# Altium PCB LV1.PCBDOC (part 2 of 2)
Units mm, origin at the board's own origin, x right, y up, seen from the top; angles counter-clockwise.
Board outline 220.06 x 100 mm, 2 copper layers (Component Side, Bottom Layer), stack 0.325 mm thick; 185 components, 114 nets, 661 pads, 212 vias.
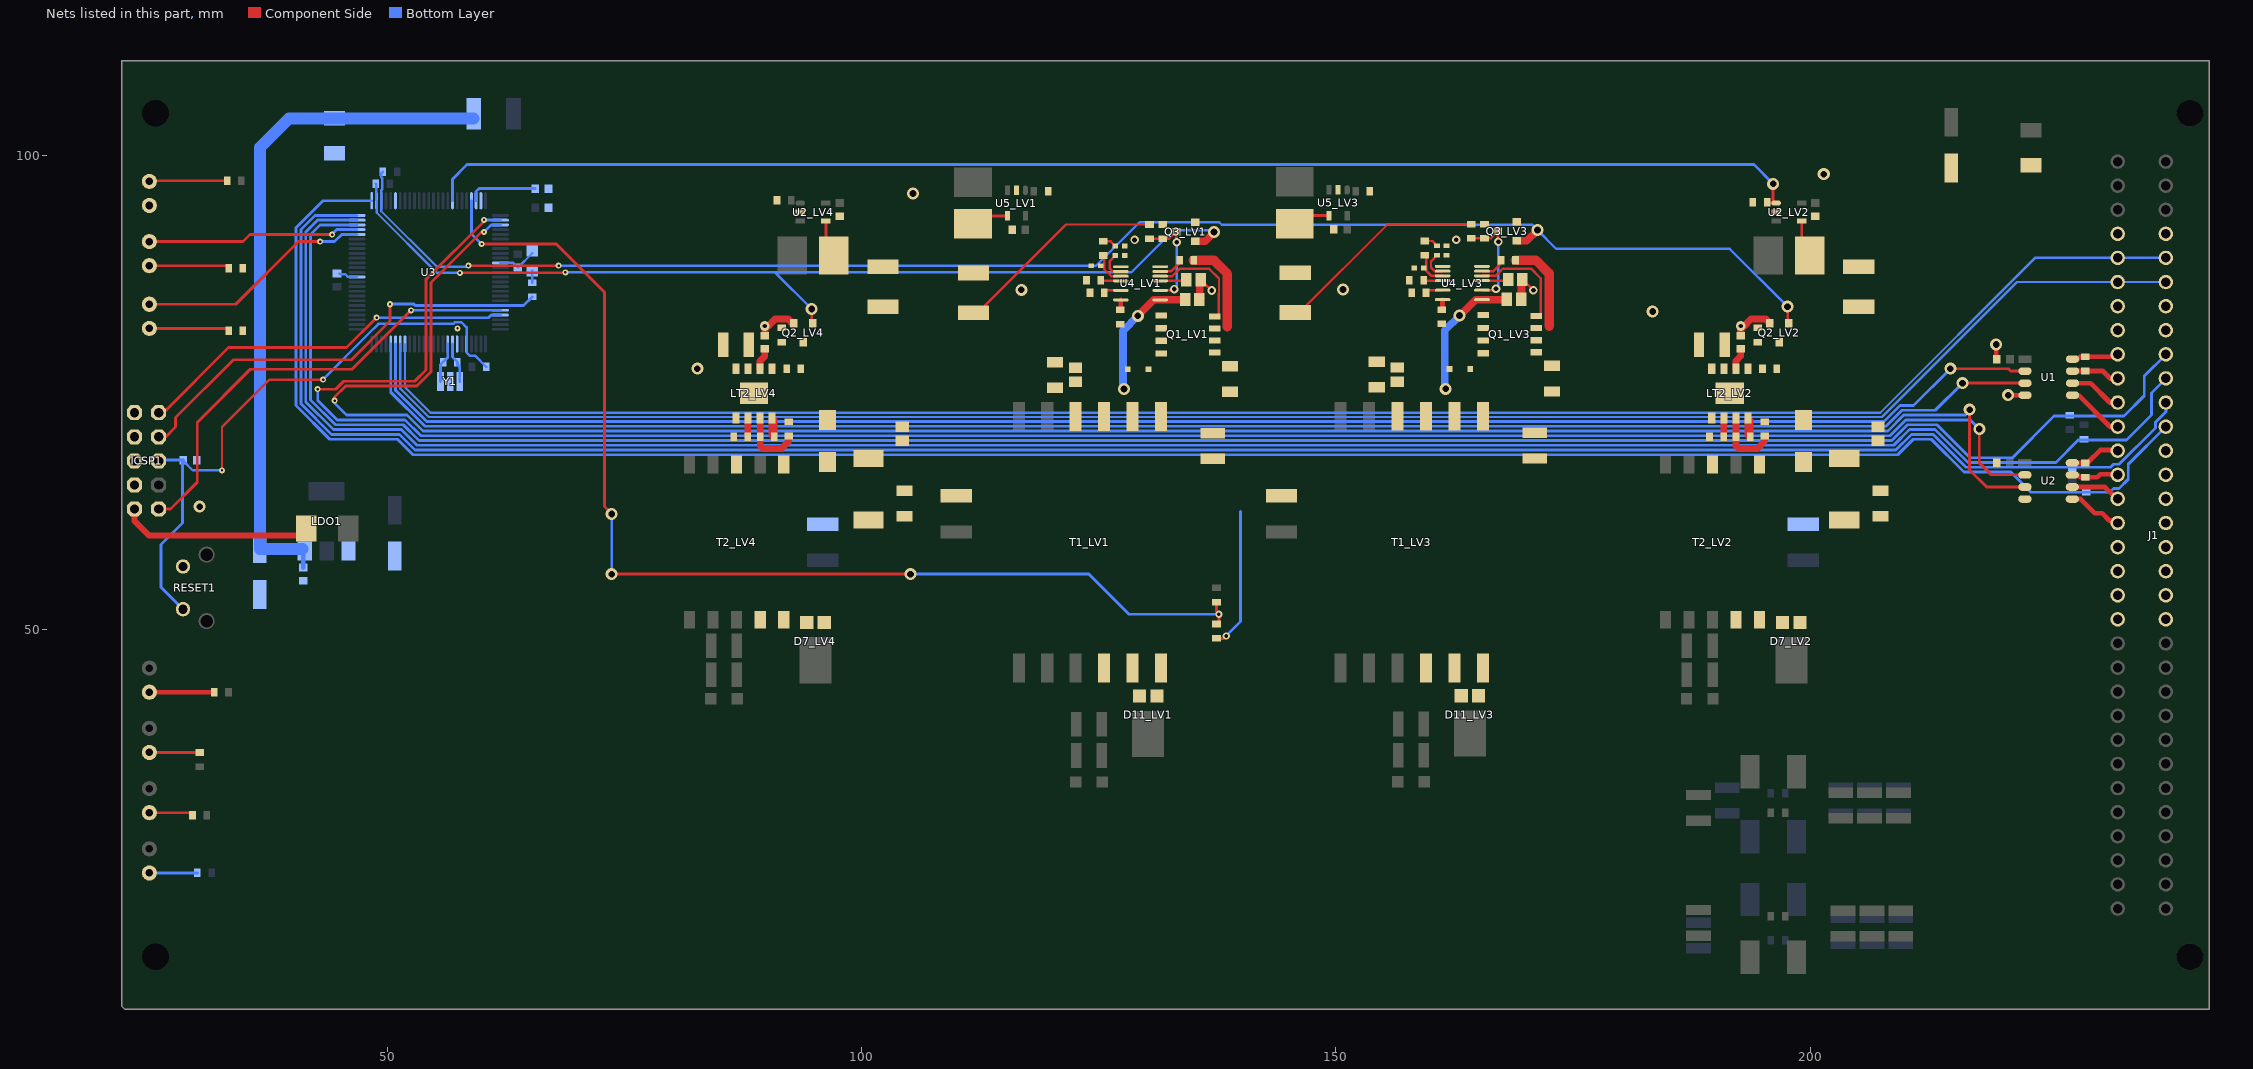
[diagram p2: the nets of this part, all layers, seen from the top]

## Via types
v1: diameter 1.27, hole 0.711, Component Side to Bottom Layer, 176 vias
v2: diameter 0.635, hole 0.254, Component Side to Bottom Layer, 17 vias
v3: diameter 0.762, hole 0.381, Component Side to Bottom Layer, 9 vias
v4: diameter 0.9, hole 0.5, Component Side to Bottom Layer, 8 vias
v5: diameter 1.016, hole 0.457, Component Side to Bottom Layer, 2 vias

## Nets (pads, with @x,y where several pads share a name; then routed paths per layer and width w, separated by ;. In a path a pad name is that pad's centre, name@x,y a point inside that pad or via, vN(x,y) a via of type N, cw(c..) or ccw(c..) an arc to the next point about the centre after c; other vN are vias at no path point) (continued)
A3: R5_LV2.2 U2_LV2.1 U3.93 | length 146
  Component Side w0.3: R5_LV2.2@195.52,94.994 U2_LV2.1@196.402,94.994 196.088,95.308 v1(196.088,97.028)
  Bottom Layer w0.3: U3.93@56.872,95.242 56.872,97.512 58.42,99.06 194.056,99.06 v1(196.088,97.028)
A_NTC: NTC.2 R_NTC.1 U3.97 | length 117.7
  Component Side w0.3: v2(59.944,90.678) 67.818,90.678 72.898,85.598 72.898,62.992 v1(73.66,62.23) ; v1(73.66,55.88) v1(105.156,55.88) ; v3@137.414,51.904 R_NTC.1@137.414,52.932 ; NTC.2@137.668,50.876 v3(137.668,51.65)
  Bottom Layer w0.3: U3.97@58.872,95.242 58.872,91.75 v2(59.944,90.678) ; v1(73.66,55.88) v1(73.66,62.23) ; v1(105.156,55.88) 123.952,55.88 128.182,51.65 v3(137.668,51.65)
ADRS0: J1.11 RADRS0.2 U3.76 | length 233.9
  Bottom Layer w0.3: U3.76@48.372,95.242 43.227,95.242 40.386,92.401 40.386,74.847 40.394,74.839 40.394,73.645 43.935,70.104 51.084,70.104 52.721,68.467 209.219,68.467 210.856,70.104 212.763,70.104 216.212,66.655 221.139,66.655 223.278,64.516 231.543,64.516 231.949,64.922 232.555,64.922 233.522,65.889 233.522,67.462 J1.11@237.49,71.43
ADRS1: J1.10 RADRS1.2 U3.75 | length 229.4
  Bottom Layer w0.3: U3.75@46.822,93.692 42.384,93.692 40.894,92.202 40.894,74.648 40.902,74.64 40.902,73.844 44.134,70.612 51.283,70.612 52.928,68.967 209.012,68.967 210.657,70.612 212.962,70.612 216.419,67.155 231.643,67.155 231.949,67.462 232.562,67.462 236.378,71.278 236.378,71.891 237.49,73.003 J1.10@237.49,73.97
ADRS2: J1.9 RADRS2.2 U3.74 | length 229
  Bottom Layer w0.3: U3.74@46.822,93.192 42.646,93.192 41.402,91.948 41.402,74.449 41.41,74.441 41.41,74.043 44.333,71.12 51.482,71.12 53.135,69.467 208.805,69.467 210.458,71.12 213.161,71.12 216.626,67.655 225.907,67.655 228.253,70.002 233.324,70.002 235.966,72.644 235.966,74.986 J1.9@237.49,76.51
ADRS3: J1.8 RADRS3.2 U3.73 | length 228
  Bottom Layer w0.3: U3.73@46.822,92.692 42.908,92.692 41.91,91.694 41.91,74.25 44.532,71.628 51.681,71.628 53.342,69.967 208.598,69.967 210.259,71.628 213.36,71.628 216.833,68.155 221.317,68.155 225.704,72.542 233.07,72.542 235.204,74.676 235.204,76.764 J1.8@237.49,79.05
AREF: AC2.2 U3.98 | length 7.3
  Bottom Layer w0.3: U3.98@59.372,95.242 59.372,96.199 59.693,96.52 AC2.2@65.594,96.52
EN1: Q2_LV2.1 Q3_LV3.1 R_pu2.2 U3.78 | length 164.9
  Component Side w0.254: v2(58.558,88.403) 58.547,88.392 v2(68.072,88.392) ; Q2_LV2.1@197.612,82.468 v1(197.612,84.074)
  Component Side w0.8: Q3_LV3.1@169.076,91.018 170.124,91.018 v1(171.251,92.145)
  Bottom Layer w0.254: R_pu2.2@49.542,98.298 49.372,98.128 49.372,97.698 49.457,97.613 49.457,96.442 49.372,96.357 U3.78@49.372,95.242 49.372,94.138 55.236,88.274 58.429,88.274 v2(58.558,88.403) ; v2(68.072,88.392) 124.714,88.392 129.301,92.979 137.692,92.979 137.961,92.71 170.686,92.71 v1(171.251,92.145) 173.226,90.17 191.516,90.17 v1(197.612,84.074)
EN2: Q2_LV4.1 Q3_LV1.1 R_pu1.2 U3.77 | length 105.1
  Component Side w0.254: v2(57.658,87.63) 68.726,87.63 v2(68.78,87.684) ; Q2_LV4.1@94.742,82.468 v1(94.742,83.82)
  Component Side w0.8: Q3_LV1.1@135.16,90.99 136.208,90.99 137.16,91.942 v1(137.16,91.948)
  Bottom Layer w0.254: R_pu1.2@48.78,97.028 48.849,96.959 48.849,95.265 U3.77@48.872,95.242 48.895,95.219 48.895,93.973 55.238,87.63 v2(57.658,87.63) ; v2(68.78,87.684) 90.878,87.684 ; v1(94.742,83.82) 90.878,87.684 ; v1(137.16,91.948) 136.991,92.117 132.861,92.117 128.428,87.684 90.878,87.684
GND: AC1.2 AC2.1 AC3.1 AC4.1 AC5.1 AC6.1 C1.2 C2.1 C3.1 C8_LV2.1 C8_LV4.1 C11_LV2.1 C11_LV4.1 C12_LV2.2 C12_LV4.2 C20.2 C21.2 C22_LV1.1 C22_LV3.1 C24_LV1.1 C24_LV3.1 C25_LV1.1 C25_LV3.1 C26_LV1.1 C26_LV3.1 C27_LV1.1 C27_LV3.1 C28_LV1.1 C28_LV3.1 C29_LV1.1 C29_LV3.1 C30.1 C31.1 C32.1 C33.1 DTVS1.2 DTVS.2 ICSP1.4 ICSP1.6 ICSP1.8 ICSP1.10 J1.3 J1.6 J1.7 J1.12 J1.13 J1.14 J1.15 J1.16 J1.17 J1.18 J1.19 J1.35 J1.38 J1.39 J1.48 J1.49 J1.50 J1.51 LDO1.1 LED1.1 LED2.C LT2_LV2.4 LT2_LV4.4 NTC.1 Q2_LV2.2 Q2_LV4.2 Q3_LV1.2 Q3_LV3.2 R3_LV1.2 R3_LV3.2 R5_LV2.1 R5_LV4.1 R7_LV2.1 R7_LV4.1 R10_LV1.1 R10_LV3.1 R14_LV1.1 R14_LV3.1 R15_LV1.1 R15_LV3.1 R16_LV1.1 R16_LV3.1 R_LED5.2 R_LED6.2 RESET1.1 Rref2_LV2.2 Rref2_LV4.2 U1.4 U2.4 U2_LV2.2 U2_LV4.2 U3.11 U3.32 U3.62 U3.81 U3.99 U4_LV1.8 U4_LV1.9 U4_LV3.8 U4_LV3.9 U5_LV1.2 U5_LV3.2 Y1.2 | length 39.2
  Component Side w0.254: C27_LV1.1@135.756,86.92 v4(136.899,85.777) ; C27_LV3.1@169.672,86.948 v4(170.815,85.805)
  Component Side w0.305: NTC.1@137.426,49.11 138.176,49.11 v3(138.43,49.364)
  Component Side w0.5: v1(219.596,80.074) 219.596,78.612 C3.1@219.658,78.55 ; v1(220.866,74.74) U1.4@222.644,74.74
  Component Side w0.75: C12_LV4.2@89.802,81.028 v5(89.802,82.042) 90.169,82.042 90.892,82.765 92.268,82.765 92.605,82.428 Q2_LV4.2@92.605,82.344 ; C12_LV2.2@192.672,81.028 v5(192.672,82.042) 193.039,82.042 193.762,82.765 195.315,82.765 Q2_LV2.2@195.736,82.344
  Component Side w0.8: C27_LV1.1@135.649,86.295 135.649,85.015 C29_LV1.1@135.744,85.015 ; C27_LV3.1@169.565,86.323 169.565,85.043 C29_LV3.1@169.66,85.043
  Bottom Layer w0.254: AC3.1@44.958,87.568 45.032,87.494 45.595,87.494 45.874,87.215 U3.62@46.799,87.215 ; U3.11@61.922,88.692 63.278,88.692 AC4.1@63.77,88.2 LED2.C@65.278,89.708
  Bottom Layer w0.305: v3(138.43,49.364) 139.954,50.888 139.954,62.484
  other v1: 30.226,62.992 82.69,77.534 183.388,83.566 116.84,85.852 150.756,85.88 105.41,96.012 201.422,98.044
  other v2: 57.404,81.788
  other v4: 128.771,91.111 162.687,91.139
MISO: ICSP1.9 U3.22 | length 40.3
  Component Side w0.3: ICSP1.9@25.908,72.898 26.416,72.898 33.274,79.756 45.72,79.756 v2(48.873,82.909)
  Bottom Layer w0.3: v2(48.873,82.909) 60.682,82.909 60.965,83.192 U3.22@61.922,83.192
MOSI: ICSP1.1 U3.21 | length 48.4
  Component Side w0.3: ICSP1.1@25.908,62.738 27.141,62.738 29.972,65.569 29.972,71.882 35.56,77.47 46.292,77.47 v2(52.514,83.692)
  Bottom Layer w0.3: v2(52.514,83.692) U3.21@61.922,83.692
NetAC6_2: AC6.2 C20.1 DTVS.1 F3.2 LDO1.3 | length 72.2
  Bottom Layer w0.508: AC6.2@41.148,56.58 LDO1.3@41.148,58.152
  Bottom Layer w1.27: LDO1.3@41.085,58.547 C20.1@36.576,58.547 36.576,100.838 39.624,103.886 F3.2@59.114,103.886
NetC11_LV2_2: C11_LV2.2 C13_LV2.2 D8_LV2.1 F2_LV2.2 LT2_LV2.3 R6_LV2.2 T2_LV2.5
NetC11_LV4_2: C11_LV4.2 C13_LV4.2 D8_LV4.1 F2_LV4.2 LT2_LV4.3 R6_LV4.2 T2_LV4.5
NetC12_LV2_1: C12_LV2.1 LT2_LV2.2 | length 2.3
  Component Side w0.7: LT2_LV2.2@192.164,77.534 192.164,78.353 192.672,78.861 C12_LV2.1@192.672,79.628
NetC12_LV4_1: C12_LV4.1 LT2_LV4.2 | length 2.3
  Component Side w0.7: LT2_LV4.2@89.294,77.534 89.294,78.353 89.802,78.861 C12_LV4.1@89.802,79.628
NetC13_LV2_1: C13_LV2.1 R8_LV2.2
NetC13_LV4_1: C13_LV4.1 R8_LV4.2
NetC22_LV1_2: C22_LV1.2 C23_LV1.2 C29_LV1.2 F1_LV1.2 R11_LV1.2 R13_LV1.1 T1_LV1.3 T1_LV1.4 U4_LV1.1 | length 36
  Component Side w0.254: F1_LV1.2@112.173,83.37 121.543,92.74 R11_LV1.2@130.35,92.74
  Component Side w0.8: v1(129.124,83.11) 130.803,84.789 U4_LV1.1@131.481,84.789 C29_LV1.2@134.105,84.789
  Bottom Layer w0.8: v1@127.561,75.476 127.561,81.547 v1(129.124,83.11)
  other v1: 127.651,75.386
NetC22_LV3_2: C22_LV3.2 C23_LV3.2 C29_LV3.2 F1_LV3.2 R11_LV3.2 R13_LV3.1 T1_LV3.3 T1_LV3.4 U4_LV3.1 | length 36
  Component Side w0.254: F1_LV3.2@146.089,83.398 155.459,92.768 R11_LV3.2@164.266,92.768
  Component Side w0.8: v1(163.04,83.138) 164.719,84.817 U4_LV3.1@165.397,84.817 C29_LV3.2@168.021,84.817
  Bottom Layer w0.8: v1@161.477,75.504 161.477,81.575 v1(163.04,83.138)
  other v1: 161.567,75.414
NetC23_LV1_1: C23_LV1.1 D9_LV1.1 R13_LV1.2
NetC23_LV3_1: C23_LV3.1 D9_LV3.1 R13_LV3.2
NetC24_LV1_2: C24_LV1.2 U4_LV1.10 | length 2.9
  Component Side w0.254: C24_LV1.2@126.747,89.46 126.179,88.892 126.179,88.091 126.458,87.812 126.482,87.812 126.505,87.789 U4_LV1.10@127.331,87.789
NetC24_LV3_2: C24_LV3.2 U4_LV3.10 | length 2.9
  Component Side w0.254: C24_LV3.2@160.663,89.488 160.02,88.845 160.02,88.194 160.374,87.84 160.398,87.84 160.421,87.817 U4_LV3.10@161.247,87.817
NetC25_LV1_2: C25_LV1.2 R4_LV1.1 | length 1.5
  Component Side w0.254: R4_LV1.1@125.469,90.972 126.251,90.972 C25_LV1.2@126.747,90.476
NetC25_LV3_2: C25_LV3.2 R4_LV3.1 | length 1.5
  Component Side w0.254: R4_LV3.1@159.385,91 160.167,91 C25_LV3.2@160.663,90.504
NetC26_LV1_2: C26_LV1.2 R4_LV1.2 U4_LV1.11 | length 3.4
  Component Side w0.254: R4_LV1.2@125.588,89.353 125.588,88.026 126.325,87.289 U4_LV1.11@127.331,87.289
NetC26_LV3_2: C26_LV3.2 R4_LV3.2 U4_LV3.11 | length 3.5
  Component Side w0.254: R4_LV3.2@159.504,89.381 159.504,87.892 160.079,87.317 U4_LV3.11@161.247,87.317
NetC27_LV1_2: C27_LV1.2 U4_LV1.5 | length 2.8
  Component Side w0.254: U4_LV1.5@131.481,86.789 C27_LV1.2@134.244,86.789
NetC27_LV3_2: C27_LV3.2 U4_LV3.5 | length 2.8
  Component Side w0.254: U4_LV3.5@165.397,86.817 C27_LV3.2@168.16,86.817
NetD1_1: D1.1 R_LED1.1 | length 5.3
  Bottom Layer w0.3: D1.1@24.67,24.384 R_LED1.1@29.984,24.384
NetD2_1: D2.1 R_LED2.1 | length 4.6
  Component Side w0.3: D2.1@24.67,30.734 R_LED2.1@29.222,30.734
NetD3_1: D3.1 R_LED3.1 | length 5.3
  Component Side w0.3: D3.1@24.67,37.084 R_LED3.1@29.984,37.084
NetD4_1: D4.1 R_LED4.1 | length 6.5
  Component Side w0.5: D4.1@25.146,43.434 R_LED4.1@31.662,43.434
NetD5_1: D5.1 R_LED5.1 | length 8.1
  Component Side w0.305: D5.1@24.924,88.392 R_LED5.1@33.032,88.392
NetD5_2: D5.2 U3.72 | length 22.4
  Component Side w0.3: D5.2@24.924,90.932 34.798,90.932 35.53,91.664 v2(44.186,91.664)
  Bottom Layer w0.3: v2@44.158,91.67 44.68,92.192 U3.72@46.822,92.192
NetD5V_2: D5V.2 ICSP1.2 | length 19.7
  Component Side w0.635: ICSP1.2@23.368,62.738 23.368,61.468 24.892,59.944 D5V.2@41.148,59.944
NetD6_1: D6.1 R_LED6.1 | length 7.9
  Component Side w0.305: D6.1@25.146,81.788 R_LED6.1@33.032,81.788
NetD6_2: D6.2 U3.71 | length 24.9
  Component Side w0.3: D6.2@24.924,84.328 34.036,84.328 40.64,90.932 v2(42.926,90.932)
  Bottom Layer w0.3: v2(42.926,90.932) 44.45,90.932 45.21,91.692 U3.71@46.822,91.692
NetD7_LV2_1: D7_LV2.1 T2_LV2.6 T2_LV2.7
NetD7_LV4_1: D7_LV4.1 T2_LV4.6 T2_LV4.7
NetD8_LV2_2: D8_LV2.2 D10_LV2.1
NetD8_LV4_2: D8_LV4.2 D10_LV4.1
NetD9_LV1_2: D9_LV1.2 Q1_LV1.5 Q1_LV1.6 Q1_LV1.7 Q1_LV1.8 R12_LV1.2 T1_LV1.1 T1_LV1.2
NetD9_LV3_2: D9_LV3.2 Q1_LV3.5 Q1_LV3.6 Q1_LV3.7 Q1_LV3.8 R12_LV3.2 T1_LV3.1 T1_LV3.2
NetD11_LV1_1: D11_LV1.1 T1_LV1.10 T1_LV1.11 T1_LV1.12
NetD11_LV3_1: D11_LV3.1 T1_LV3.10 T1_LV3.11 T1_LV3.12
NetF1_LV1_1: F1_LV1.1 Rsense1_LV1.2 U5_LV1.4 | length 2.8
  Component Side w0.3: Rsense1_LV1.2@112.596,93.646 U5_LV1.4@115.368,93.646
NetF1_LV3_1: F1_LV3.1 Rsense1_LV3.2 U5_LV3.4 | length 2.8
  Component Side w0.3: Rsense1_LV3.2@146.512,93.674 U5_LV3.4@149.284,93.674
NetF2_LV2_1: F2_LV2.1 Rsense2_LV2.2 U2_LV2.4 | length 2.8
  Component Side w0.3: Rsense2_LV2.2@199.102,90.322 U2_LV2.4@199.102,93.094
NetF2_LV4_1: F2_LV4.1 Rsense2_LV4.2 U2_LV4.4 | length 2.8
  Component Side w0.3: Rsense2_LV4.2@96.232,90.322 U2_LV4.4@96.232,93.094
NetJ1_40: J1.40 R1.2 U1.8 | length 4.4
  Component Side w0.508: U1.8@227.644,78.55 228.177,78.55 228.419,78.792 R1.2@228.994,78.792 J1.40@231.974,78.792
NetJ1_41: J1.41 R1.1 U1.7 | length 5.1
  Component Side w0.508: U1.7@227.644,77.28 228.982,77.28 R1.1@228.994,77.292 230.816,77.292 231.598,76.51 J1.41@232.41,76.51
NetJ1_42: J1.42 U1.6 | length 5.6
  Component Side w0.508: U1.6@227.644,76.01 229.558,76.01 231.598,73.97 J1.42@232.41,73.97
NetJ1_43: J1.43 U1.5 | length 6.1
  Component Side w0.508: U1.5@227.644,74.74 228.288,74.74 231.598,71.43 J1.43@232.41,71.43
NetJ1_44: J1.44 R2.1 U2.8 | length 5.4
  Component Side w0.508: U2.8@227.624,67.605 228.962,67.605 R2.1@228.974,67.617 ; R2.1@228.974,67.593 229.213,67.593 230.574,68.954 J1.44@232.41,68.954
NetJ1_45: J1.45 R2.2 U2.7 | length 5
  Component Side w0.508: U2.7@227.624,66.335 228.17,66.335 228.412,66.093 R2.2@228.974,66.093 230.253,66.093 230.574,66.414 J1.45@232.41,66.414
NetJ1_46: J1.46 U2.6 | length 5.2
  Component Side w0.508: U2.6@227.624,65.065 231.049,65.065 231.534,64.58 231.59,64.58 J1.46@232.296,63.874
NetJ1_47: J1.47 U2.5 | length 5.4
  Component Side w0.508: U2.5@227.624,63.795 228.509,63.795 230.01,62.294 230.772,62.294 231.534,61.532 J1.47@232.098,61.532
NetLED1_2: LED1.2 RLED1.2 | length 8
  Component Side w0.3: LED1.2@25.146,97.344 RLED1.2@33.12,97.344
NetLED2_A: LED2.A RLED2.1 | length 1.2
  Bottom Layer w0.254: RLED2.1@65.278,86.602 LED2.A@65.278,87.85
NetLT2_LV2_1: LT2_LV2.1 Q2_LV2.3 R6_LV2.1 R7_LV2.2
NetLT2_LV2_6: LT2_LV2.6 Rfb2_LV2.1 | length 2
  Component Side w0.7: Rfb2_LV2.1@190.882,70.339 LT2_LV2.6@190.882,72.315
NetLT2_LV2_7: LT2_LV2.7 Rref2_LV2.1 Rtc2_LV2.2 | length 6.9
  Component Side w0.7: LT2_LV2.7@192.176,72.315 Rtc2_LV2.2@192.176,70.339 192.176,69.418 192.466,69.128 194.426,69.128 195.212,69.914 Rref2_LV2.1@195.212,70.434
NetLT2_LV2_8: LT2_LV2.8 Rtc2_LV2.1 | length 3.9
  Component Side w0.7: Rtc2_LV2.1@193.434,70.497 LT2_LV2.8@193.434,72.327 193.676,72.085 Rtc2_LV2.1@193.676,70.339
NetLT2_LV4_1: LT2_LV4.1 Q2_LV4.3 R6_LV4.1 R7_LV4.2
NetLT2_LV4_6: LT2_LV4.6 Rfb2_LV4.1 | length 2
  Component Side w0.7: Rfb2_LV4.1@88.012,70.339 LT2_LV4.6@88.012,72.315
NetLT2_LV4_7: LT2_LV4.7 Rref2_LV4.1 Rtc2_LV4.2 | length 6.9
  Component Side w0.7: LT2_LV4.7@89.306,72.315 Rtc2_LV4.2@89.306,70.339 89.306,69.418 89.596,69.128 91.556,69.128 92.342,69.914 Rref2_LV4.1@92.342,70.434
NetLT2_LV4_8: LT2_LV4.8 Rtc2_LV4.1 | length 3.9
  Component Side w0.7: Rtc2_LV4.1@90.564,70.497 LT2_LV4.8@90.564,72.327 90.806,72.085 Rtc2_LV4.1@90.806,70.339
NetQ1_LV1_1: Q1_LV1.1 Q1_LV1.2 Q1_LV1.3 R9_LV1.1 R16_LV1.2 | length 9.7
  Component Side w1: R9_LV1.1@134.982,88.952 137.153,88.952 138.55,87.555 138.55,81.967
NetQ1_LV1_4: Q1_LV1.4 U4_LV1.6 | length 11.6
  Component Side w0.254: U4_LV1.6@131.481,87.289 132.755,87.289 133.529,88.063 136.645,88.063 137.676,87.032 137.676,85.455 137.668,85.447 137.668,83.11 Q1_LV1.4@136.932,83.11
NetQ1_LV3_1: Q1_LV3.1 Q1_LV3.2 Q1_LV3.3 R9_LV3.1 R16_LV3.2 | length 9.7
  Component Side w1: R9_LV3.1@168.898,88.98 171.069,88.98 172.466,87.583 172.466,81.995
NetQ1_LV3_4: Q1_LV3.4 U4_LV3.6 | length 11.6
  Component Side w0.254: U4_LV3.6@165.397,87.317 166.819,87.317 167.283,87.781 167.283,87.783 167.591,88.091 170.561,88.091 171.592,87.06 171.592,85.483 171.577,85.468 171.577,83.138 Q1_LV3.4@170.848,83.138
NetQ3_LV1_3: Q3_LV1.3 R11_LV1.1 R14_LV1.2 U4_LV1.3 | length 11.1
  Component Side w0.254: R11_LV1.1@130.35,91.24 R14_LV1.2@131.747,91.24 132.41,91.24 Q3_LV1.3@133.16,91.99 v4@133.16,90.93 ; U4_LV1.3@131.481,85.789 132.824,85.789 v4(132.959,85.924) 133.114,85.924 v4@133.255,85.783
  Bottom Layer w0.254: v4(132.959,85.924) 133.213,86.178 v4(133.213,90.877)
NetQ3_LV3_3: Q3_LV3.3 R11_LV3.1 R14_LV3.2 U4_LV3.3 | length 11.1
  Component Side w0.254: R11_LV3.1@164.266,91.268 R14_LV3.2@165.663,91.268 166.326,91.268 Q3_LV3.3@167.076,92.018 v4@167.076,90.958 ; U4_LV3.3@165.397,85.817 166.74,85.817 v4(166.875,85.952) 167.03,85.952 v4@167.171,85.811
  Bottom Layer w0.254: v4(166.875,85.952) 167.129,86.206 v4(167.129,90.905)
NetR3_LV1_1: R3_LV1.1 U4_LV1.14 | length 1.5
  Component Side w0.254: R3_LV1.1@125.85,85.789 U4_LV1.14@127.331,85.789
NetR3_LV3_1: R3_LV3.1 U4_LV3.14 | length 1.5
  Component Side w0.254: R3_LV3.1@159.766,85.817 U4_LV3.14@161.247,85.817
NetR9_LV1_2: R9_LV1.2 U4_LV1.7 | length 2.3
  Component Side w0.254: U4_LV1.7@131.481,87.789 132.613,87.789 133.407,88.583 R9_LV1.2@133.482,88.583
NetR9_LV3_2: R9_LV3.2 U4_LV3.7 | length 2.3
  Component Side w0.254: U4_LV3.7@165.397,87.817 166.604,87.817 R9_LV3.2@167.398,88.611
NetR12_LV1_1: R12_LV1.1 U4_LV1.16 | length 1
  Component Side w0.5: R12_LV1.1@127.331,83.817 U4_LV1.16@127.331,84.789
NetR12_LV3_1: R12_LV3.1 U4_LV3.16 | length 1
  Component Side w0.5: R12_LV3.1@161.247,83.845 U4_LV3.16@161.247,84.817
NetR15_LV1_2: R15_LV1.2 U4_LV1.12 | length 2
  Component Side w0.254: R15_LV1.2@125.31,86.789 U4_LV1.12@127.331,86.789
NetR15_LV3_2: R15_LV3.2 U4_LV3.12 | length 1.9
  Component Side w0.254: R15_LV3.2@159.346,86.817 U4_LV3.12@161.247,86.817
RESET: AC1.1 ICSP1.5 R_pu5.1 RESET1.2 U3.30 | length 65.3
  Component Side w0.254: v2(32.577,66.817) 32.577,71.389 37.577,76.389 v2(43.245,76.389)
  Bottom Layer w0.254: AC1.1@28.411,67.898 29.492,66.817 v2(32.577,66.817) ; v2(43.245,76.389) 48.02,81.215 49.071,82.265 56.97,82.265 57.137,82.432 57.823,82.432 58.372,81.883 U3.30@58.372,80.142 58.395,80.119 58.395,79.194 58.674,78.915 59.249,78.915 R_pu5.1@60.44,77.724
  Bottom Layer w0.3: ICSP1.5@25.988,67.898 AC1.1@28.411,67.898 ; RESET1.2@28.473,52.186 26.162,54.497 26.162,59.008 28.411,61.257 AC1.1@28.411,67.898 ; AC1.1@28.51,67.898 AC1.1@28.411,67.898
RX0: U2.2 U3.2 | length 220.2
  Component Side w0.3: v2(42.672,75.376) 44.573,75.376 45.417,76.22 52.907,76.22 54.102,77.415 54.102,86.96 60.198,93.056 v2(60.198,93.218)
  Component Side w0.305: v1(217.818,71.184) 217.818,67.628 219.088,66.358 U2.2@222.602,66.358
  Bottom Layer w0.3: v2(42.672,75.376) 42.672,74.195 44.731,72.136 51.88,72.136 53.549,70.467 208.391,70.467 210.06,72.136 216.866,72.136 v1(217.818,71.184) ; v2(60.198,93.218) 60.224,93.192 U3.2@61.922,93.192
RX1: U1.2 U3.45 | length 180.4
  Component Side w0.3: v1(214.77,77.534) 220.866,77.534 221.12,77.28 U1.2@222.644,77.28
  Bottom Layer w0.3: U3.45@50.872,80.142 50.872,75.265 54.17,71.967 207.77,71.967 209.463,73.66 210.896,73.66 v1(214.77,77.534)
SCK: ICSP1.7 RLED2.2 U3.20 | length 47.2
  Component Side w0.3: ICSP1.7@25.908,70.358 26.67,70.358 27.686,71.374 27.686,72.39 33.782,78.486 46.228,78.486 50.292,82.55 v2(50.292,84.328)
  Bottom Layer w0.3: v2@50.292,84.359 52.79,84.359 52.958,84.192 U3.20@61.922,84.192 64.368,84.192 RLED2.2@65.278,85.102
SCL: J1.4 J1.36 U3.43 | length 198
  Bottom Layer w0.254: U3.43@51.872,80.142 51.872,75.582 54.556,72.898 207.384,72.898 223.696,89.21 J1.36@232.41,89.21 J1.4@237.49,89.21
SDA: J1.5 J1.37 U3.44 | length 198
  Bottom Layer w0.254: U3.44@51.372,80.142 51.372,75.44 54.368,72.444 207.572,72.444 221.798,86.67 J1.37@232.41,86.67 J1.5@237.49,86.67
SW_LV2: D10_LV2.2 LT2_LV2.5 R8_LV2.1 Rfb2_LV2.2 T2_LV2.3
SW_LV4: D10_LV4.2 LT2_LV4.5 R8_LV4.1 Rfb2_LV4.2 T2_LV4.3
TX0: U2.3 U3.3 | length 218.9
  Component Side w0.3: v2(44.45,74.168) 44.45,74.546 45.624,75.72 53.114,75.72 54.61,77.216 54.61,86.614 59.944,91.948 v2(60.198,91.948) ; v1(216.802,73.216) 216.802,66.866 218.603,65.065 U2.3@222.624,65.065
  Bottom Layer w0.254: v1@216.866,73.152 v1@217.21,73.152
  Bottom Layer w0.3: v2(44.45,74.168) 44.45,73.914 45.72,72.644 52.079,72.644 53.756,70.967 208.184,70.967 209.861,72.644 216.358,72.644 v1@216.866,73.152 ; v2(60.198,91.948) 60.942,92.692 U3.3@61.922,92.692
TX1: U1.3 U3.46 | length 180.7
  Component Side w0.3: v1(216.04,76.01) U1.3@222.644,76.01
  Bottom Layer w0.3: U3.46@50.372,80.142 50.372,75.058 53.963,71.467 207.977,71.467 209.662,73.152 213.182,73.152 v1(216.04,76.01)
XTAL1: AR2.1 U3.34 Y1.3 | length 4.3
  Bottom Layer w0.3: Y1.3@55.626,76.2 55.626,77.966 AR2.1@55.892,78.232 56.372,78.712 U3.34@56.372,80.142
XTAL2: AR2.2 U3.33 Y1.1 | length 4.3
  Bottom Layer w0.3: U3.33@56.872,80.142 56.872,78.752 AR2.2@57.392,78.232 57.392,77.948 57.642,77.698 Y1.1@57.642,76.2
pads on no net: ICSP1.3 J1.0@240.03,15.55 J1.0@240.03,104.45 RESET1.0 T1_LV1.5 T1_LV1.6 T1_LV3.5 T1_LV3.6 T2_LV2.1 T2_LV2.2 T2_LV2.4 T2_LV2.8 T2_LV4.1 T2_LV4.2 T2_LV4.4 T2_LV4.8 U3.1 U3.4 U3.5 U3.6 U3.7 U3.8 U3.9 U3.12 U3.13 U3.14 U3.15 U3.16 U3.17 U3.18 U3.19 U3.23 U3.24 U3.25 U3.26 U3.27 U3.28 U3.29 U3.35 U3.36 U3.37 U3.38 U3.39 U3.40 U3.41 U3.42 U3.47 U3.48 U3.49 U3.50 U3.51 U3.52 U3.53 U3.54 U3.55 U3.56 U3.57 U3.58 U3.59 U3.60 U3.63 U3.64 U3.65 U3.66 U3.67 U3.68 U3.69 U3.70 U3.79 U3.82 U3.83 U3.84 U3.85 U3.86 U3.87 U3.88 U3.89 U3.90 U3.91 U3.92

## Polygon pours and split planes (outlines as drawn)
GND on Bottom Layer "GND_L02_P643" (solid, pour order 1209): 22.86,109.354 238.16,109.354 238.16,60.84 22.86,60.84
+5V on Bottom Layer "Component Side-No Net" (solid, pour order 1191): 42.814,57.268 42.814,59.368 40.314,59.368 40.314,65.968 40.386,66.04 53.34,66.04 53.34,59.368 44.45,59.368 44.45,57.304 44.414,57.268
+5VA_FILTERED on Bottom Layer "Component Side-No Net" (solid, pour order 1190): 197.612,24.384 197.612,19.812 210.95,19.812 210.95,24.254 210.82,24.384
-5VB_FILTERED on Bottom Layer "Component Side-No Net" (solid, pour order 1193): 197.612,25.4 197.612,31 197.878,30.734 219.202,30.734 213.868,25.4
-5VB on Bottom Layer "Component Side-No Net" (solid, pour order 1192): 178.308,25.4 178.308,31.242 194.818,31.242 194.818,25.4
+5VA on Bottom Layer "Component Side-No Net" (solid, pour order 1203): 124.714,18.828 124.714,24.384 194.818,24.384 194.818,18.732
+5VGNDA on Bottom Layer "Component Side-No Net" (solid, pour order 1204): 108.458,11.722 108.458,16.764 211.074,16.764 211.074,11.664
-5VGNDA on Bottom Layer "-5VGNDA_L02_P642" (solid, pour order 1206): 102.248,33.02 75.692,33.02 75.692,57.976 102.248,57.976
-5VB on Bottom Layer "Component Side-No Net" (solid, pour order 1199): 187.706,25.368 178.3,25.368 178.3,57.944 187.706,57.944
-5VGNDB on Bottom Layer "Component Side-No Net" (solid, pour order 1194): 194.818,33.274 194.818,38.227 218.821,38.227 213.868,33.274
+5VA_FILTERED on Bottom Layer "Component Side-No Net" (solid, pour order 1195): 238.506,29.718 238.506,33.274 238.506,34.036 238.252,34.29 231.902,34.29 223.774,34.29 213.868,24.384 210.82,24.384 210.82,19.266 210.75,19.196 210.858,19.304 214.122,19.304 216.154,19.304 226.568,29.718 237.998,29.718
+5VGNDA on Bottom Layer "Component Side-No Net" (solid, pour order 1196): 238.506,24.638 238.506,28.194 238.506,28.702 237.998,29.21 231.648,29.21 228.6,29.21 216.154,16.764 216.012,16.622 211.074,16.622 211.074,11.754 211.144,11.684 215.138,11.684 218.44,11.684 231.394,24.638
-5VB_FILTERED on Bottom Layer "Component Side-No Net" (solid, pour order 1189): 219.036,30.734 224.79,36.488 224.79,36.83 219.964,36.83 213.868,30.734 213.868,30.646
GND on Bottom Layer "Component Side-No Net" (solid, pour order 1201): 23.045,60.96 23.114,60.891 23.114,51.308 55.88,51.308 65.532,60.96
GND on Bottom Layer "GNDbottom" (solid, pour order 1207): 142.399,101.785 142.399,63.298 108.444,63.298 108.444,101.785
+5VGNDA on Bottom Layer "Component Side-No Net" (solid, pour order 1205): 123.222,11.7 123.222,52.832 108.458,52.832 108.458,11.681
+5VA on Bottom Layer "Component Side-No Net" (solid, pour order 1200): 124.746,18.796 124.746,47.646 135.795,47.646 135.795,18.796
+5VB on Bottom Layer "Component Side-No Net" (solid, pour order 1197): 158.662,32.852 158.662,47.674 169.711,47.674 169.711,32.852
GND on Bottom Layer "GNDbottom" (solid, pour order 1208): 176.315,101.813 176.315,63.326 142.36,63.326 142.36,101.813
+5VGNDB on Bottom Layer "Component Side-No Net" (solid, pour order 1198): 157.138,32.866 157.138,52.324 142.374,52.324 142.374,32.847
-5VGNDB on Bottom Layer "-5VGNDB_L02_P638" (solid, pour order 1202): 205.346,33.369 189.992,33.369 189.992,58.071 205.346,58.071
48V on Component Side "Component Side-No Net" (solid, pour order 1148): 238.252,101.6 238.252,95.758 231.394,95.758 231.394,101.6
+5VB_FILTERED on Component Side "Component Side-No Net" (solid, pour order 1159): 197.612,38.1 197.612,32.512 210.82,32.512 210.82,38.1
-5VA_FILTERED on Component Side "Component Side-No Net" (solid, pour order 1170): 197.612,12.192 197.612,17.526 197.866,17.78 227.33,17.78 227.33,12.192
+5VGNDB on Component Side "Component Side-No Net" (solid, pour order 1176): 210.82,25.4 210.82,30.05 142.494,30.05 142.494,25.4
+5VB on Component Side "Component Side-No Net" (solid, pour order 1173): 194.818,32.385 194.818,38.227 158.662,38.227 158.662,32.385
-5VGNDA on Component Side "Component Side-No Net" (solid, pour order 1182): 226.822,20.066 231.14,24.384 86.106,24.384 86.106,20.066
-5VA on Component Side "Component Side-No Net" (solid, pour order 1183): 194.818,12.16 194.818,17.78 75.832,17.78 75.832,12.16
48V on Component Side "Component Side-No Net" (solid, pour order 1184): 238.252,101.41 87.008,101.41 87.008,106.49 238.252,106.49
GND on Component Side "Component Side-No Net" (solid, pour order 1187): 210.058,100.394 228.6,100.394 228.6,95.504 228.854,95.25 238.252,95.25 238.252,50.292 210.058,50.292
48V on Component Side "Component Side-No Net" (solid, pour order 1157): 92.596,91.312 92.596,87.248 87.008,87.248 87.008,106.49 90.31,106.49 90.31,92.074 91.072,91.312 92.85,91.312
48V on Component Side "Component Side-No Net" (solid, pour order 1156): 195.466,91.312 195.466,87.248 189.878,87.248 189.878,105.22 193.18,105.22 193.18,92.074 193.942,91.312 195.72,91.312
GND on Component Side "GND_L01_P626" (solid, pour order 1188): 84.043,60.634 84.043,75.112 87.091,75.112 87.091,78.16 86.583,78.16 86.583,78.284 86.075,78.792 86.075,92.638 86.075,106.608 22.86,106.608 22.86,60.634
NetC11_LV4_2 on Component Side "NETC11_LV4_2_L01_P618" (solid, remove dead copper, pour order 1174): 106.058,86.17 87.516,86.17 87.516,77.026 91.834,77.026 91.834,66.612 92.596,66.612 95.644,70.93 96.914,70.93 106.058,70.93
GND on Component Side "GND_L01_P577" (solid, pour order 1143): 81.674,76.01 92.938,76.01 92.938,71.692 91.834,71.692 91.834,72.809 90.92,73.724 81.674,73.724
NetLT2_LV4_1 on Component Side "NETLT2_LV4_1_L01_P568" (solid, pour order 1132): 95.194,80.845 90.056,80.845 90.056,76.772 93.507,76.772
NetC13_LV4_1 on Component Side "NETC13_LV4_1_L01_P575" (solid, pour order 1134): 106.058,64.072 103.264,64.072 103.264,70.422 106.058,70.422
NetD8_LV4_2 on Component Side "NETD8_LV4_2_L01_P586" (solid, pour order 1146): 103.01,69.152 95.39,69.152 95.39,64.58 103.01,64.58
NetF2_LV4_1 on Component Side "NETF2_LV4_1_L01_P581" (solid, pour order 1145): 106.058,87.248 97.676,87.248 97.676,88.553 97.676,91.312 98.819,91.312 106.058,91.312
-5VA on Component Side "-5VA_L01_P619" (solid, pour order 1177): 84.976,54.102 75.832,54.102 75.832,17.78 84.976,17.78
SW_LV4 on Component Side "SW_LV4_L01_P595" (solid, pour order 1155): 106.058,60.516 85.23,60.516 85.23,72.962 87.262,72.962 87.262,65.088 87.516,64.834 89.294,63.056 89.802,62.548 106.058,62.548
NetD7_LV4_1 on Component Side "NETD7_LV4_1_L01_P604" (solid, pour order 1151): 102.248,50.038 102.248,54.102 88.024,54.102 88.024,50.038
-5VGNDA on Component Side "-5VGNDA_L01_P620" (solid, pour order 1179): 102.248,49.53 102.248,20.066 86.246,20.066 86.246,49.53
GND on Component Side "GND_L01_P564" (solid, pour order 1129): 94.628,78.296 94.628,75.502 94.628,73.47 92.85,73.47 92.85,76.518 93.104,76.518 93.104,78.296
NetLT2_LV2_1 on Component Side "NETLT2_LV2_1_L01_P571" (solid, pour order 1133): 198.064,80.845 192.926,80.845 192.926,76.772 196.377,76.772
GND on Component Side "GND_L01_P578" (solid, pour order 1142): 184.544,76.01 195.808,76.01 195.808,71.692 194.704,71.692 194.704,72.809 193.79,73.724 184.544,73.724
GND on Component Side "GND_L01_P566" (solid, pour order 1128): 197.498,78.296 197.498,75.502 197.498,73.47 195.72,73.47 195.72,76.518 195.974,76.518 195.974,78.296
NetC13_LV2_1 on Component Side "NETC13_LV2_1_L01_P574" (solid, pour order 1135): 208.928,64.072 206.134,64.072 206.134,70.422 208.928,70.422
NetD8_LV2_2 on Component Side "NETD8_LV2_2_L01_P587" (solid, pour order 1147): 205.88,69.152 198.26,69.152 198.26,64.58 205.88,64.58
NetF2_LV2_1 on Component Side "NETF2_LV2_1_L01_P582" (solid, pour order 1144): 208.928,87.44 200.546,87.44 200.546,88.745 200.546,91.504 201.689,91.504 208.928,91.504
-5VB on Component Side "-5VB_L01_P610" (solid, pour order 1169): 187.846,57.976 178.448,57.976 178.448,41.974 187.846,41.974
SW_LV2 on Component Side "SW_LV2_L01_P594" (solid, pour order 1154): 208.928,60.516 188.1,60.516 188.1,72.962 190.132,72.962 190.132,65.088 190.386,64.834 192.164,63.056 192.672,62.548 208.928,62.548
NetD7_LV2_1 on Component Side "NETD7_LV2_1_L01_P605" (solid, pour order 1158): 205.372,50.038 205.372,55.372 191.656,55.372 191.656,50.038
-5VGNDB on Component Side "-5VGNDB_L01_P607" (solid, pour order 1165): 205.372,49.683 205.372,41.974 189.116,41.974 189.116,49.683
GND on Component Side "GND_L01_P624" (solid, pour order 1180): 186.83,60.516 186.83,74.994 189.878,74.994 189.878,78.042 189.37,78.042 189.37,78.166 188.862,78.674 188.862,99.314 176.022,99.314 176.022,60.516
NetC11_LV2_2 on Component Side "NETC11_LV2_2_L01_P617" (solid, remove dead copper, pour order 1175): 208.928,86.17 190.386,86.17 190.386,77.026 194.704,77.026 194.704,66.612 195.466,66.612 198.514,70.93 199.784,70.93 208.928,70.93
GND on Component Side "Component Side-No Net" (solid, pour order 1164): 106.898,93.09 106.898,100.456 91.072,100.456 91.072,93.09
GND on Component Side "Component Side-No Net" (solid, pour order 1166): 211.214,100.394 193.548,100.394 193.548,92.774 211.214,92.774
+5VB_FILTERED on Component Side "Component Side-No Net" (solid, pour order 1167): 238.506,45.212 238.506,49.022 237.998,49.53 232.156,49.53 224.282,49.53 212.852,38.1 210.82,38.1 210.82,32.512 213.106,32.512 225.806,45.212
+5VGNDB on Component Side "Component Side-No Net" (solid, pour order 1168): 238.506,40.132 238.506,43.688 237.744,44.45 232.156,44.45 227.672,44.45 213.868,30.646 210.566,30.646 210.566,25.654 210.696,25.524 210.82,25.4 213.868,25.4 214.376,25.4 229.108,40.132
+5VA on Component Side "Component Side-No Net" (solid, pour order 1162): 124.783,41.46 124.783,33.967 124.783,32.951 135.884,32.951 135.884,41.46
48V on Component Side "Component Side-No Net" (solid, pour order 1141): 113.778,95.536 109.714,95.536 109.714,101.854 113.778,101.854
NetF1_LV1_1 on Component Side "NETF2_LV4_1_L01_P581" (solid, pour order 1136): 113.697,87.878 109.83,87.879 109.83,93.593 113.697,93.593
NetC22_LV1_2 on Component Side "Component Side-No Net" (solid, pour order 1171): 115.221,85.148 115.221,70.231 135.284,70.231 135.284,68.636 138.431,68.636 138.431,66.513 138.171,66.166 110.111,66.166 110.111,85.148
+5VGNDA on Component Side "Component Side-No Net" (solid, pour order 1178): 123.193,60.96 123.193,44.356 123.193,32.951 108.458,32.951 108.458,60.96
NetD11_LV1_1 on Component Side "Component Side-No Net" (solid, pour order 1153): 124.76,47.561 124.76,44.386 124.76,42.222 135.861,42.222 135.861,47.561
NetC22_LV1_2 on Component Side "Component Side-No Net" (solid, pour order 1149): 119.5,76.125 119.5,74.855 120.135,74.855 120.591,74.399 120.591,69.394 126.231,69.394 126.231,74.22 127.474,74.22 128.517,75.067 128.517,76.706 119.5,76.706
NetD9_LV1_2 on Component Side "Component Side-No Net" (solid, pour order 1126): 126.739,82.306 126.739,80.57 127.501,79.808 130.041,79.808 130.041,82.306
NetQ1_LV1_1 on Component Side "Component Side-No Net" (solid, pour order 1138): 136.541,82.221 141.217,82.221 141.217,77.236 136.541,77.236
NetD9_LV1_2 on Component Side "Component Side-No Net" (solid, pour order 1160): 127.882,70.918 127.882,73.966 129.152,73.966 130.041,74.855 130.041,78.03 130.041,82.706 130.826,83.491 136.001,83.491 136.001,72.433 134.486,70.918
NetC23_LV1_1 on Component Side "Component Side-No Net" (solid, pour order 1131): 128.263,77.014 119.5,77.014 119.5,78.919 128.263,78.919
GND on Component Side "GNDtop" (solid, pour order 1185): 115.602,99.314 115.602,85.402 108.444,85.402 108.444,63.425 142.399,63.425 142.399,99.314
GND on Component Side "GNDtop" (solid, pour order 1186): 149.518,99.342 149.518,85.43 142.36,85.43 142.36,63.453 176.315,63.453 176.315,99.342
NetC23_LV3_1 on Component Side "Component Side-No Net" (solid, pour order 1130): 162.179,77.042 153.416,77.042 153.416,78.947 162.179,78.947
NetD9_LV3_2 on Component Side "Component Side-No Net" (solid, pour order 1161): 161.798,70.946 161.798,73.994 163.068,73.994 163.957,74.883 163.957,78.058 163.957,82.734 164.742,83.519 169.917,83.519 169.917,72.461 168.402,70.946
NetQ1_LV3_1 on Component Side "Component Side-No Net" (solid, pour order 1139): 170.457,82.249 175.133,82.249 175.133,77.264 170.457,77.264
NetD9_LV3_2 on Component Side "Component Side-No Net" (solid, pour order 1127): 160.655,82.334 160.655,80.598 161.417,79.836 163.957,79.836 163.957,82.334
NetC22_LV3_2 on Component Side "Component Side-No Net" (solid, pour order 1150): 153.416,76.153 153.416,74.883 154.051,74.883 154.507,74.427 154.507,69.422 160.147,69.422 160.147,74.248 161.39,74.248 162.433,75.095 162.433,76.734 153.416,76.734
NetD11_LV3_1 on Component Side "Component Side-No Net" (solid, pour order 1152): 158.676,47.589 158.676,44.414 158.676,42.25 169.777,42.25 169.777,47.589
+5VGNDB on Component Side "Component Side-No Net" (solid, pour order 1181): 157.109,60.96 157.109,44.384 157.109,25.4 142.374,25.4 142.374,60.96
NetC22_LV3_2 on Component Side "Component Side-No Net" (solid, pour order 1172): 149.137,85.176 149.137,70.259 169.2,70.259 169.2,68.664 172.347,68.664 172.347,66.541 172.087,66.194 144.027,66.194 144.027,85.176
NetF1_LV3_1 on Component Side "NETF2_LV4_1_L01_P581" (solid, pour order 1137): 147.613,87.906 143.746,87.907 143.746,93.621 147.613,93.621
48V on Component Side "Component Side-No Net" (solid, pour order 1140): 147.694,95.564 143.63,95.564 143.63,101.882 147.694,101.882
+5VB on Component Side "Component Side-No Net" (solid, pour order 1163): 158.699,41.488 158.699,33.995 158.699,32.979 169.8,32.979 169.8,41.488

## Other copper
Component Side:
  pour cut-out: 91.834,71.692 91.834,70.676 93.104,70.676 93.104,71.526 92.938,71.692
  pour cut-out: 194.704,71.692 194.704,70.676 195.974,70.676 195.974,71.526 195.808,71.692

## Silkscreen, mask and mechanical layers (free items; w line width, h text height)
Top Overlay:
  drawing of 1087 lines, arcs and shapes, not listed
  text "-5V B" at 32.512,44.958 h1.52
  text "+5V B" at 32.512,37.592 h1.52
  text "HEP" at 50.14,34.493 h0.8
  text "Rev. 2.0 November 2015" at 48.26,33.02 h0.8
  text "G-2 LV Rack Power supply" at 48.26,31.496 h0.8
  text "-5V A" at 31.75,30.734 h1.52
  text "https://goo.gl/EopGqf" at 48.26,29.972 h0.8
  text "+5V A" at 32.258,24.638 h1.52
Mechanical 1:
  the board outline again, w0.127
Mechanical 6:
  lines w0.5: 22,109.982 22,10.414 22,10.352 22.352,10 172.974,10 242.062,10 242.062,110 22.018,110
